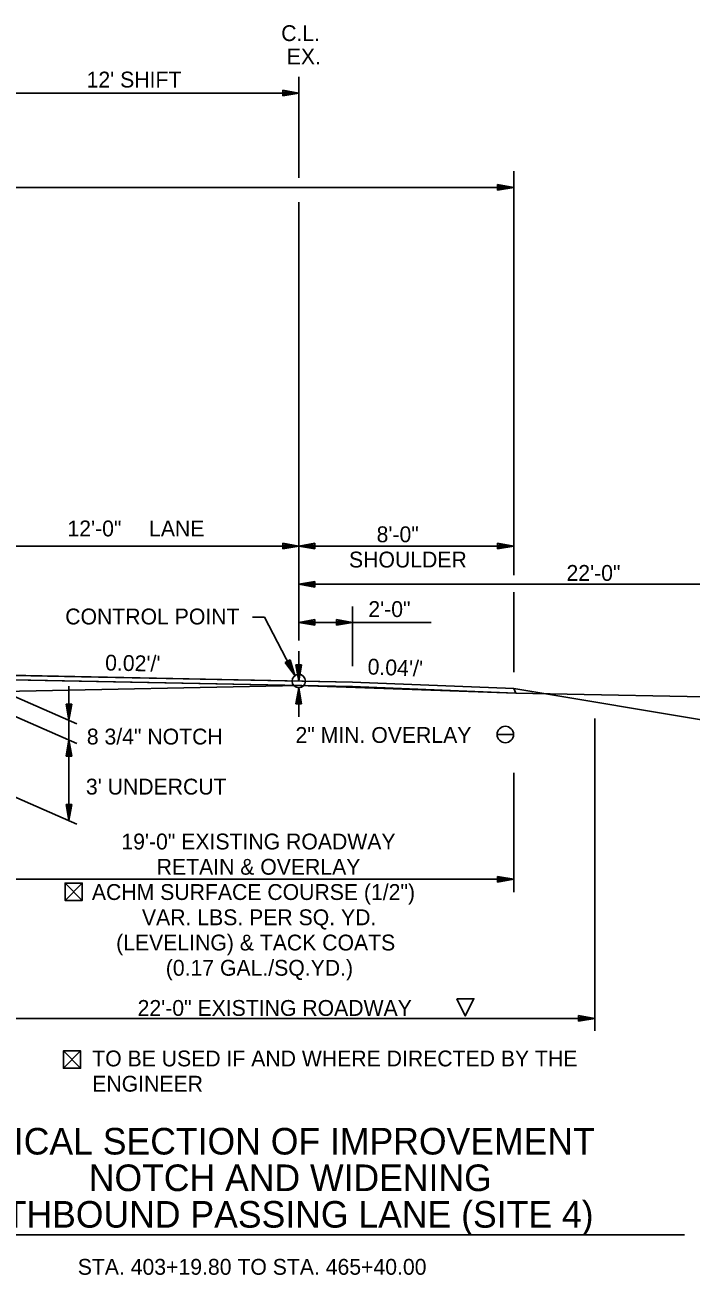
# Model space of a CAD drawing. Extents: x 1398565 to 1398920, y 1968324 to 1968581.
# Drawn here: x 1398843.78 to 1398868.57, y 1968324.27 to 1968370.8 of the extents above; entities that cross this region are included whole.
import ezdxf

# ---------------------------------------------------------------- set-up
doc = ezdxf.new("R2010")
doc.units = 0
for name, color, linetype in [('10', 7, 'Continuous'), ('19', 7, 'Continuous'), ('42', 7, 'Continuous'), ('7', 7, 'Continuous'), ('Level 9', 7, 'Continuous')]:
    doc.layers.add(name, color=color, linetype=linetype)

msp = doc.modelspace()

# ---------------------------------------------------------------- linework, layer by layer
at = {"layer": '10'}
for p, q in [((1398861.353, 1968344.392), (1398861.965, 1968344.392)), ((1398845.267, 1968338.859), (1398845.908, 1968338.218)), ((1398845.908, 1968338.859), (1398845.267, 1968338.218)), ((1398845.648, 1968338.218), (1398845.66, 1968338.218)), ((1398845.207, 1968332.612), (1398845.848, 1968331.971)), ((1398845.848, 1968332.612), (1398845.207, 1968331.971))]:
    msp.add_line(p, q, dxfattribs=at)
for points in [[(1398845.66, 1968338.218), (1398845.908, 1968338.218), (1398845.908, 1968338.859), (1398845.267, 1968338.859), (1398845.267, 1968338.218), (1398845.648, 1968338.218)], [(1398845.6, 1968331.971), (1398845.848, 1968331.971), (1398845.848, 1968332.612), (1398845.207, 1968332.612), (1398845.207, 1968331.971), (1398845.588, 1968331.971)]]:
    msp.add_lwpolyline(points, dxfattribs=at)
msp.add_lwpolyline([(1398859.846, 1968334.558), (1398860.487, 1968334.558), (1398860.167, 1968333.917)], close=True, dxfattribs=at)
msp.add_circle((1398861.659, 1968344.392), 0.306, dxfattribs=at)
msp.add_arc((1398861.659, 1968344.392), 0.306, 0, 180, dxfattribs=at)
at = {"layer": '19'}
for p, q in [((1398853.969, 1968368.269), (1398841.969, 1968368.269)), ((1398853.369, 1968368.374), (1398853.369, 1968368.164)), ((1398853.969, 1968368.269), (1398853.369, 1968368.374)), ((1398853.809, 1968368.284), (1398853.369, 1968368.319)), ((1398853.369, 1968368.164), (1398853.969, 1968368.269)), ((1398853.369, 1968368.214), (1398853.809, 1968368.254)), ((1398861.969, 1968350.317), (1398861.969, 1968365.359)), ((1398811.969, 1968364.759), (1398861.969, 1968364.759)), ((1398861.369, 1968364.864), (1398861.369, 1968364.654)), ((1398861.969, 1968364.759), (1398861.369, 1968364.864)), ((1398861.809, 1968364.774), (1398861.369, 1968364.809)), ((1398861.369, 1968364.654), (1398861.969, 1968364.759)), ((1398861.369, 1968364.704), (1398861.809, 1968364.744)), ((1398843.969, 1968351.403), (1398831.969, 1968351.403)), ((1398861.969, 1968351.403), (1398843.969, 1968351.403)), ((1398853.369, 1968351.298), (1398853.369, 1968351.508)), ((1398853.369, 1968351.508), (1398853.969, 1968351.403)), ((1398853.369, 1968351.453), (1398853.809, 1968351.418)), ((1398853.969, 1968351.403), (1398853.369, 1968351.298)), ((1398853.809, 1968351.388), (1398853.369, 1968351.348)), ((1398853.969, 1968351.403), (1398854.569, 1968351.508)), ((1398854.569, 1968351.298), (1398853.969, 1968351.403)), ((1398854.129, 1968351.418), (1398854.569, 1968351.453)), ((1398854.569, 1968351.348), (1398854.129, 1968351.388)), ((1398854.569, 1968351.508), (1398854.569, 1968351.298)), ((1398861.369, 1968351.298), (1398861.369, 1968351.508)), ((1398861.369, 1968351.508), (1398861.969, 1968351.403)), ((1398861.369, 1968351.453), (1398861.809, 1968351.418)), ((1398861.969, 1968351.403), (1398861.369, 1968351.298)), ((1398861.809, 1968351.388), (1398861.369, 1968351.348)), ((1398853.969, 1968349.982), (1398854.569, 1968350.088)), ((1398853.969, 1968349.982), (1398875.969, 1968349.982)), ((1398854.569, 1968349.878), (1398853.969, 1968349.982)), ((1398854.129, 1968349.997), (1398854.569, 1968350.033)), ((1398854.569, 1968349.928), (1398854.129, 1968349.967)), ((1398854.569, 1968350.088), (1398854.569, 1968349.878)), ((1398861.969, 1968346.708), (1398861.969, 1968349.689)), ((1398855.969, 1968346.94), (1398855.969, 1968349.162)), ((1398853.969, 1968348.562), (1398854.569, 1968348.667)), ((1398858.895, 1968348.562), (1398853.969, 1968348.562)), ((1398854.569, 1968348.457), (1398853.969, 1968348.562)), ((1398854.129, 1968348.577), (1398854.569, 1968348.612)), ((1398854.569, 1968348.507), (1398854.129, 1968348.547)), ((1398854.569, 1968348.667), (1398854.569, 1968348.457)), ((1398855.369, 1968348.457), (1398855.369, 1968348.667)), ((1398855.369, 1968348.667), (1398855.969, 1968348.562)), ((1398855.369, 1968348.612), (1398855.809, 1968348.577)), ((1398855.969, 1968348.562), (1398855.369, 1968348.457)), ((1398855.809, 1968348.547), (1398855.369, 1968348.507)), ((1398853.646, 1968347.166), (1398853.46, 1968347.071)), ((1398853.502, 1968347.089), (1398853.738, 1968346.72)), ((1398853.761, 1968346.729), (1398853.6, 1968347.137)), ((1398853.823, 1968346.583), (1398853.646, 1968347.166)), ((1398853.969, 1968347.489), (1398853.969, 1968346.38)), ((1398841.969, 1968346.62), (1398855.969, 1968346.34)), ((1398853.46, 1968347.071), (1398853.823, 1968346.583)), ((1398854.074, 1968346.98), (1398853.864, 1968346.98)), ((1398853.864, 1968346.98), (1398853.969, 1968346.38)), ((1398853.919, 1968346.98), (1398853.954, 1968346.54)), ((1398853.969, 1968346.38), (1398854.074, 1968346.98)), ((1398853.984, 1968346.54), (1398854.024, 1968346.98)), ((1398841.969, 1968346.453), (1398855.969, 1968346.173)), ((1398845.41, 1968346.196), (1398845.41, 1968344.92)), ((1398855.969, 1968346.34), (1398861.969, 1968346.1)), ((1398855.969, 1968346.173), (1398862.054, 1968345.93)), ((1398842.969, 1968345.993), (1398845.712, 1968344.784)), ((1398853.969, 1968346.13), (1398853.864, 1968345.53)), ((1398853.954, 1968345.97), (1398853.919, 1968345.53)), ((1398854.074, 1968345.53), (1398853.969, 1968346.13)), ((1398853.969, 1968346.13), (1398853.969, 1968345.048)), ((1398854.024, 1968345.53), (1398853.984, 1968345.97)), ((1398861.969, 1968346.1), (1398875.969, 1968343.767)), ((1398861.969, 1968346.1), (1398862.054, 1968345.93)), ((1398842.969, 1968345.264), (1398845.712, 1968344.055)), ((1398845.515, 1968345.52), (1398845.305, 1968345.52)), ((1398845.305, 1968345.52), (1398845.41, 1968344.92)), ((1398845.36, 1968345.52), (1398845.395, 1968345.08)), ((1398845.41, 1968344.92), (1398845.515, 1968345.52)), ((1398845.425, 1968345.08), (1398845.465, 1968345.52)), ((1398853.864, 1968345.53), (1398854.074, 1968345.53)), ((1398845.41, 1968344.92), (1398845.41, 1968341.188)), ((1398864.983, 1968333.357), (1398864.983, 1968344.989)), ((1398845.41, 1968344.188), (1398845.305, 1968343.588)), ((1398845.395, 1968344.028), (1398845.36, 1968343.588)), ((1398845.515, 1968343.588), (1398845.41, 1968344.188)), ((1398845.465, 1968343.588), (1398845.425, 1968344.028)), ((1398845.305, 1968343.588), (1398845.515, 1968343.588)), ((1398861.969, 1968342.968), (1398861.969, 1968338.522)), ((1398842.969, 1968342.264), (1398845.712, 1968341.055)), ((1398845.515, 1968341.788), (1398845.305, 1968341.788)), ((1398845.305, 1968341.788), (1398845.41, 1968341.188)), ((1398845.36, 1968341.788), (1398845.395, 1968341.348)), ((1398845.41, 1968341.188), (1398845.515, 1968341.788)), ((1398845.425, 1968341.348), (1398845.465, 1968341.788)), ((1398861.969, 1968339.006), (1398842.983, 1968339.006)), ((1398861.369, 1968338.901), (1398861.369, 1968339.111)), ((1398861.369, 1968339.111), (1398861.969, 1968339.006)), ((1398861.369, 1968339.056), (1398861.809, 1968339.021)), ((1398861.969, 1968339.006), (1398861.369, 1968338.901)), ((1398861.809, 1968338.991), (1398861.369, 1968338.951)), ((1398864.983, 1968333.825), (1398842.983, 1968333.825)), ((1398864.383, 1968333.72), (1398864.383, 1968333.93)), ((1398864.383, 1968333.93), (1398864.983, 1968333.825)), ((1398864.383, 1968333.875), (1398864.823, 1968333.84)), ((1398864.983, 1968333.825), (1398864.383, 1968333.72)), ((1398864.823, 1968333.81), (1398864.383, 1968333.77)), ((1398839.35, 1968325.765), (1398868.33, 1968325.765))]:
    msp.add_line(p, q, dxfattribs=at)
msp.add_lwpolyline([(1398852.244, 1968348.76), (1398852.69, 1968348.76), (1398853.823, 1968346.583)], dxfattribs=at)
msp.add_lwpolyline([(1398811.884, 1968345.77), (1398815.969, 1968345.933), (1398841.969, 1968346.453), (1398855.969, 1968346.173), (1398862.054, 1968345.93), (1398861.969, 1968346.1), (1398855.969, 1968346.34), (1398841.969, 1968346.62), (1398815.969, 1968346.1), (1398811.969, 1968345.94)], close=True, dxfattribs=at)
at = {"layer": '42'}
for points in [[(1398842.969, 1968345.993), (1398853.969, 1968346.213)], [(1398853.969, 1968346.213), (1398862.054, 1968345.93), (1398870.969, 1968345.753), (1398879.824, 1968343.293), (1398884.905, 1968343.835), (1398901.722, 1968343.746)]]:
    msp.add_lwpolyline(points, dxfattribs=at)
at = {"layer": '7'}
for p, q in [((1398853.969, 1968365.11), (1398853.969, 1968368.869)), ((1398853.969, 1968347.89), (1398853.969, 1968364.207))]:
    msp.add_line(p, q, dxfattribs=at)
at = {"layer": 'Level 9'}
msp.add_circle((1398853.969, 1968346.38), 0.25, dxfattribs=at)

# ---------------------------------------------------------------- texts
at = {"layer": '10'}
for s, height, p in [('12\'-0" ', 0.59, (1398845.357, 1968351.767)), ('LANE', 0.59, (1398848.395, 1968351.767)), ('8\'-0" ', 0.59, (1398856.865, 1968351.549)), ('SHOULDER', 0.59, (1398855.838, 1968350.609)), ('22\'-0"', 0.59, (1398863.934, 1968350.111)), ('CONTROL POINT', 0.59001, (1398845.274, 1968348.489)), ('2\'-0"', 0.59, (1398856.558, 1968348.765)), ('8 3/4" NOTCH', 0.59001, (1398846.078, 1968344.02)), ('2" MIN. OVERLAY', 0.59001, (1398853.845, 1968344.079)), ("3' UNDERCUT", 0.59001, (1398846.045, 1968342.157)), ('19\'-0" EXISTING ROADWAY', 0.59001, (1398847.364, 1968340.113)), ('RETAIN & OVERLAY', 0.59001, (1398848.678, 1968339.173)), ('ACHM SURFACE COURSE (1/2")', 0.59001, (1398846.267, 1968338.233)), ('VAR. LBS. PER SQ. YD.', 0.59001, (1398848.13, 1968337.293)), ('(LEVELING) & TACK COATS', 0.59001, (1398847.168, 1968336.353)), ('(0.17 GAL./SQ.YD.)', 0.59001, (1398849.017, 1968335.413)), ('22\'-0" EXISTING ROADWAY', 0.59001, (1398847.969, 1968333.918)), ('TO BE USED IF AND WHERE DIRECTED BY THE ', 0.59001, (1398846.28, 1968332.038)), ('ENGINEER', 0.59, (1398846.28, 1968331.098)), ('STA. 403+19.80 TO STA. 465+40.00', 0.59001, (1398845.74, 1968324.282))]:
    msp.add_text(s, height=height, rotation=360, dxfattribs=at).set_placement(p)
at = {"layer": '19'}
msp.add_text('C.L.', height=0.59, dxfattribs=at).set_placement((1398853.314, 1968370.203))
for s, height, rotation, p in [('EX.', 0.59, 360, (1398853.52, 1968369.335)), ("12' SHIFT", 0.59, 360, (1398846.07, 1968368.475)), ("0.02'/'", 0.59, 358.8542, (1398846.755, 1968346.774)), ("0.04'/'", 0.59, 357.7094, (1398856.521, 1968346.629)), ('TYPICAL SECTION OF IMPROVEMENT', 0.98999, 360, (1398840.787, 1968328.758)), ('NOTCH AND WIDENING', 0.98999, 360, (1398846.15, 1968327.397)), ('SOUTHBOUND PASSING LANE (SITE 4)', 0.98999, 360, (1398840.152, 1968326.036))]:
    msp.add_text(s, height=height, rotation=rotation, dxfattribs=at).set_placement(p)

doc.saveas('drawing.dxf')
